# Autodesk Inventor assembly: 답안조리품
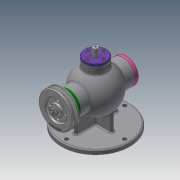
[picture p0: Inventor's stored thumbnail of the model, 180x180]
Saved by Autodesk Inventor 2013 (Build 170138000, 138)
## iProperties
Created: 2020-08
Part Number: 답안조리품
Document SubType Name: Assembly
Designer: user
Mass: 3181.57 g
Surface Area: 2199.14 cm^2
Volume: 880.123 cm^3
Density: 3.61491 g/cm^3
Author: user
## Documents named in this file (18)
- C:\Users\user\Desktop\거위\답안조리품.iam
- C:\Users\user\Desktop\거위\본체.ipt
- C:\Users\user\Desktop\거위\Ű 3x3x12.ipt
- C:\Users\user\Desktop\거위\V-벨트풀리.ipt
- C:\Users\user\Desktop\거위\너트 M8.ipt
- C:\Users\user\Desktop\거위\뒤커버.ipt
- C:\Users\user\Desktop\거위\멈춤링 15x1.ipt
- C:\Users\user\Desktop\거위\멈춤링 35x1.6.ipt
- 멈춤링 35x1.6.ipt
- C:\Users\user\Desktop\거위\베어링 6202.ipt
- 베어링 6202.ipt
- C:\Users\user\Desktop\거위\볼트 M4.ipt
- C:\Users\user\Desktop\거위\상부커버.ipt
- C:\Users\user\Desktop\거위\슬라이드.ipt
- C:\Users\user\Desktop\거위\앞커버.ipt
- C:\Users\user\Desktop\거위\오일 실 15 30 7.ipt
- C:\Users\user\Desktop\거위\칼라.ipt
- C:\Users\user\Desktop\거위\편심축.ipt
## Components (2 placed, 2 different names)
1. Ű 3x3x12:1
2. V-벨트풀리:1
